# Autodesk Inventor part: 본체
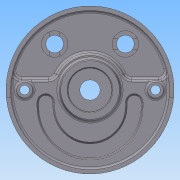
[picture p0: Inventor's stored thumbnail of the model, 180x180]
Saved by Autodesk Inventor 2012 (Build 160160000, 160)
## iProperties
Created: 2015-04
Part Number: 본체
Material: 알루미늄-6061
Document SubType Name: Modeling
Designer: net
Density: 2.71 g/cm^3
Mass: 1038.84 g
Surface Area: 1020.36 cm^2
Volume: 383.336 cm^3
Author: net
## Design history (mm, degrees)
sketch "스케치1"
  geometry: C1 r 95 at (0, 0); 1 further point
  constraints: 1 centre point, 1 coincident
  dimensions: "d0" = 190 diameter of C1
extrude "돌출1" new body sketch "스케치1" distance "d1" = 32; taper "d2" = 0 deg
feature "쉘1" dims "d3" = 5
feature "면 이동1"
sketch "스케치4"
  geometry: L1 (-76.916, 12)-(-47.117, 12); L2 (47.117, 12)-(76.916, 12); C1 r 25 at (0, 0) reference; C2 r 90 at (0, 0) reference; C3 r 90 at (0, 0) reference; A1 r 42 centre (0, 0) between (38.056, 17.769) and (-38.056, 17.769); A2 r 90 centre (0, 0) between (86.53, 24.75) and (-86.53, 24.75); A3 r 10 centre (-47.117, 22) between (-47.117, 12) and (-38.056, 17.769); A4 r 10 centre (-76.916, 22) between (-86.53, 24.75) and (-76.916, 12); A5 r 10 centre (47.117, 22) between (38.056, 17.769) and (47.117, 12); A6 r 10 centre (76.916, 22) between (76.916, 12) and (86.53, 24.75); 5 further points
  constraints: 16 point on circle, 8 tangent, 6 centre point, 4 end point, 4 point on line, 3 equal radius, 2 coincident, 2 horizontal, 1 collinear, 1 vertical alignment
  dimensions: "d10" = 84 diameter of A1; "d11" = 180 diameter of A2; "d13" = 12 distance from line of L2 C1.centre; "d14" = 10 radius of A3
extrude "돌출4" cut sketch "스케치4" distance "d15" = 7; taper "d16" = 0 deg
sketch "스케치5"
  geometry: L1 (-47.117, 12)-(-76.916, 12) reference; L2 (-59, -19)-(59, -19); L3 (-59, -14)-(59, -14); L4 (41, -19)-(41, -14); L5 (59, -19)-(59, -14); L6 (-59, -19)-(-59, -14); L7 (-41, -19)-(-41, -14); A1 r 90 centre (0, 0) between (-86.53, 24.75) and (86.53, 24.75) reference; A2 r 59 centre (0, -19) between (-59, -19) and (59, -19); A3 r 41 centre (0, -19) between (-41, -19) and (41, -19); A4 r 9 centre (-50, -14) between (-41, -14) and (-59, -14); A5 r 9 centre (50, -14) between (59, -14) and (41, -14); 2 further points
  constraints: 12 end point, 8 point on circle, 8 point on line, 4 centre point, 4 tangent, 3 parallel, 3 perpendicular, 2 coincident, 2 vertical alignment, 1 midpoint
  dimensions: "d17" = 19 distance from line of A1.centre L2; "d20" = 59 radius of A2; "d21" = 41 radius of A3; "d23" = 5 distance between parallel lines of L2 L3
extrude "돌출5" cut sketch "스케치5" distance "d24" = 7; taper "d25" = 0 deg
sketch "스케치6"
  geometry: C1 r 35 at (0, 0); A1 r 42 centre (0, 0) between (38.056, 17.769) and (-38.056, 17.769) reference
  constraints: 1 centre point, 1 coincident
  dimensions: "d26" = 70 diameter of C1
extrude "돌출6" join sketch "스케치6" distance "d27" = 10; taper "d28" = 0 deg
sketch "스케치7"
  geometry: C1 r 35 at (0, 0) reference; C2 r 25 at (0, 0)
  constraints: 1 centre point, 1 coincident
  dimensions: "d29" = 50 diameter of C2
extrude "돌출7" cut sketch "스케치7" distance "d30" = 15; taper "d31" = 0 deg
sketch "스케치8"
  geometry: C1 r 25 at (0, 0) reference; C2 r 11.5 at (0, 0)
  constraints: 1 centre point, 1 coincident
  dimensions: "d32" = 23 diameter of C2
extrude "돌출8" cut sketch "스케치8" stored distance "d33" = 15; taper "d34" = 0 deg
sketch "스케치9"
  geometry: L1 (0, 0)-(-94.638, -8.28); L2 (0, 0)-(94.638, -8.28); L3 (-47.117, 12)-(-76.916, 12) reference; L4 (76.916, 12)-(47.117, 12) reference; C1 r 90 at (0, 0) reference; C2 r 95 at (0, 0) reference; A1 r 95 centre (0, 0) between (-94.638, -8.28) and (94.638, -8.28); A2 r 90 centre (0, 0) between (-89.658, -7.844) and (89.658, -7.844); 1 further point
  constraints: 4 end point, 4 point on circle, 3 coincident, 2 centre point, 2 concentric, 2 point on line
  dimensions: "d35" = 5 deg angle of L3 L1; "d36" = 5 deg angle of L4 L2
extrude "돌출9" cut sketch "스케치9" distance "d37" = 5; taper "d38" = 0 deg
sketch "스케치10"
  geometry: C1 r 15 at (-40, 52); C2 r 15 at (40, 52); A1 r 42 centre (0, 0) between (38.056, 17.769) and (-38.056, 17.769) reference
  constraints: 2 centre point, 1 equal radius, 1 horizontal alignment
  dimensions: "d39" = 52 vertical distance of C2.centre A1.centre; "d40" = 80 distance of C1.centre C2.centre; "d41" = 40 horizontal distance of A1.centre C2.centre; "d42" = 30 diameter of C1
extrude "돌출10" join sketch "스케치10" stored distance "d43" = 5; taper "d44" = 0 deg
sketch "스케치11"
  geometry: C1 r 15 at (0, 0) reference; C2 r 15 at (80, 0) reference; C3 r 10 at (0, 0); C4 r 10 at (80, 0); 1 further point
  constraints: 2 centre point, 2 coincident, 1 equal radius
  dimensions: "d45" = 20 diameter of C4
extrude "돌출11" cut sketch "스케치11" stored distance "d46" = 5; taper "d47" = 0 deg
sketch "스케치12"
  geometry: L1 (-6, 13.748)-(-6, -13.748); L2 (6, 13.748)-(6, -13.748); C1 r 10 at (0, 0) reference; A1 r 15 centre (0, 0) between (-6, 13.748) and (6, 13.748) reference; 1 further point
  constraints: 4 end point, 4 point on circle, 2 vertical
  dimensions: "d48" = 12 distance between parallel lines of L2 L1; "d49" = 6 distance from line of C1.centre L1
extrude "돌출12" cut sketch "스케치12" distance "d50" = 3; taper "d51" = 0 deg
sketch "스케치13"
  geometry: L1 (-13.748, 6)-(13.748, 6); L2 (-13.748, -6)-(13.748, -6); C1 r 10 at (0, 0) reference; A1 r 15 centre (0, 0) between (13.748, -6) and (13.748, 6) reference; 1 further point
  constraints: 4 end point, 4 point on circle, 1 horizontal, 1 parallel
  dimensions: "d52" = 12 distance between parallel lines of L2 L1; "d53" = 6 distance from line of L1 C1.centre
extrude "돌출13" cut sketch "스케치13" distance "d54" = 3; taper "d55" = 0 deg
sketch "스케치15"
  geometry: C1 r 35 at (0, 0) reference; C2 r 9 at (-74, 0); C3 r 9 at (74, 0); A1 r 90 centre (0, 0) between (-86.53, 24.75) and (86.53, 24.75) reference
  constraints: 2 centre point, 2 horizontal alignment, 1 equal radius
  dimensions: "d58" = 148 distance of C2.centre C3.centre; "d59" = 74 distance of C1.centre C3.centre (= 0.5 x d58); "d60" = 18 diameter of C3
extrude "돌출14" join sketch "스케치15" stored distance "d61" = 3; taper "d62" = 0 deg
sketch "스케치14"
  geometry: C1 r 11.5 at (0, 0) reference; A1 r 41 centre (0, -19) between (-41, -19) and (41, -19) reference; 2 further points
  constraints: 2 horizontal alignment
  dimensions: "d56" = 148 distance of point (74, 0) point (-74, 0); "d70" = 74 distance of C1.centre point (-74, 0) (= 0.5 x d56)
hole "구멍1" sketch "스케치14" diameter "d63" = 11; stored, may be unused: countersink angle "d67" = 90 deg, drill point angle "d69" = 118 deg; dims "d64" = 6, "d65" = 18, "d66" = 11, "d68" = 8
sketch "스케치16"
  geometry: L1 (39.44, -39.44)-(47.244, -47.244); L2 (-39.44, -39.44)-(-47.244, -47.244); C1 r 11.5 at (0, 0) reference; C2 r 95 at (0, 0) reference; A1 r 51 centre (0, 0) between (-32.699, -39.138) and (32.699, -39.138); A2 r 72 centre (0, 0) between (-46.97, -54.569) and (46.97, -54.569); A3 r 5 centre (-35.904, -42.975) between (-32.699, -39.138) and (-39.44, -39.44); A4 r 5 centre (-43.709, -50.78) between (-47.244, -47.244) and (-46.97, -54.569); A5 r 5 centre (35.904, -42.975) between (39.44, -39.44) and (32.699, -39.138); A6 r 5 centre (43.709, -50.78) between (46.97, -54.569) and (47.244, -47.244); 5 further points
  constraints: 17 point on circle, 8 tangent, 6 centre point, 6 point on line, 4 end point, 3 equal radius, 2 coincident, 1 vertical alignment
  dimensions: "d71" = 51 radius of A1; "d72" = 72 radius of A2; "d73" = 90 deg angle of L1 L2; "d101" = 5 radius of A3
extrude "돌출15" join sketch "스케치16" distance "d74" = 5; taper "d75" = 0 deg
chamfer "모따기1" distance "d76" = 1; stored, may be unused: second distance "d77" = 2, angle "d78" = 45 deg
fillet "모깎기1" dims "d79" = 3
chamfer "모따기2" distance "d80" = 1; stored, may be unused: second distance "d81" = 2, angle "d82" = 45 deg
chamfer "모따기3" distance "d83" = 1; stored, may be unused: second distance "d84" = 2, angle "d85" = 45 deg
chamfer "모따기4" distance "d86" = 10; stored, may be unused: second distance "d87" = 2, angle "d88" = 10 deg
fillet "모깎기3" dims "d90" = 3
fillet "모깎기4" dims "d91" = 3
fillet "모깎기5" dims "d92" = 5
fillet "모깎기9" dims "d99" = 0.3
fillet "모깎기10" dims "d100" = 3
fillet "모깎기11" dims "d105" = 5
sketch "스케치19"
  geometry: C1 r 68 at (0, 0); A1 r 56 centre (0, 0) between (-35.904, -42.975) and (35.904, -42.975) reference
  constraints: 1 centre point, 1 coincident, 1 other
  dimensions: "d106" = 136 diameter of C1
feature "엠보싱3" sketch "스케치19" dims "d10" = 84, "d11" = 180, "d13" = 12, "d14" = 10, "d107" = 0.5, "d108" = 0
fillet "모깎기12" dims "d109" = 3
node "솔리드1"
other parameters: "d12" = 12
